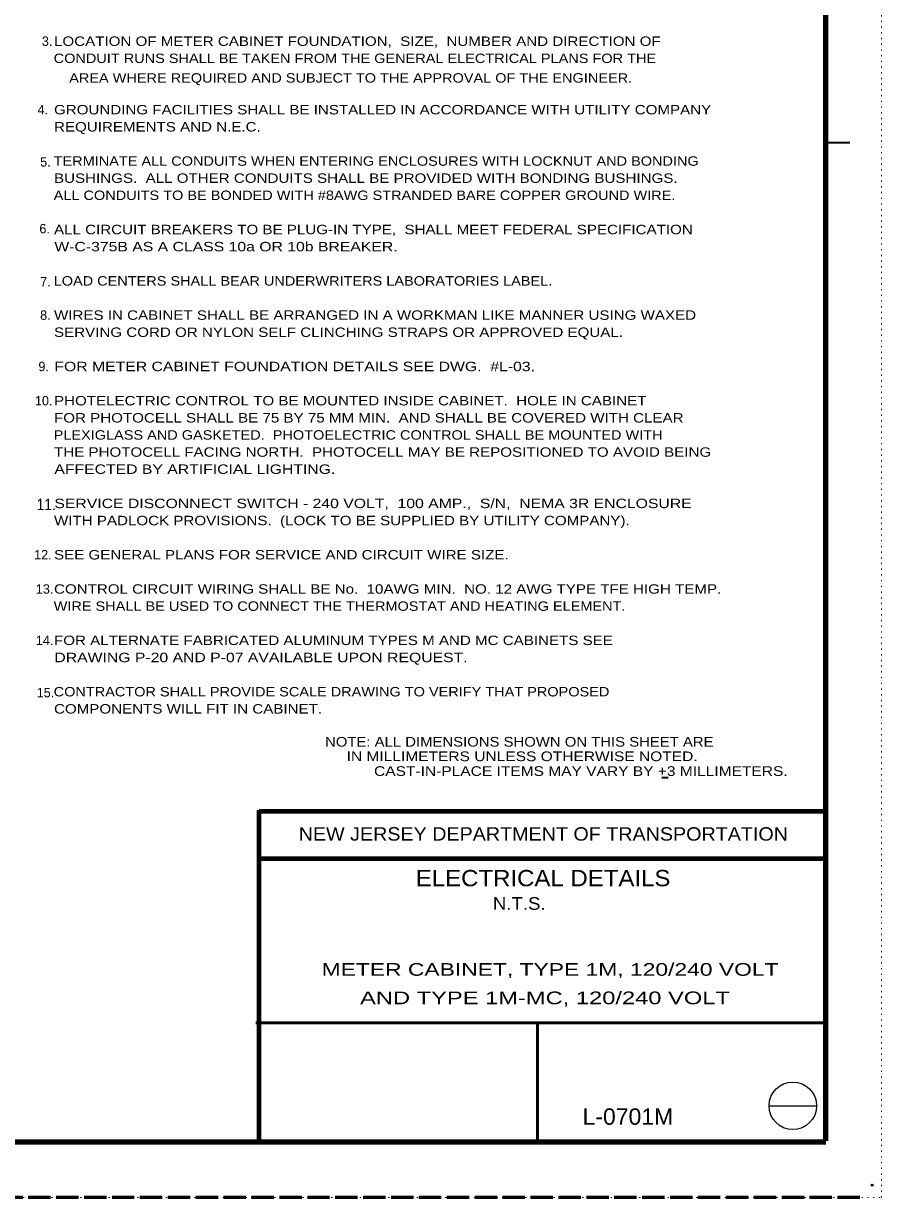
# Model space of a CAD drawing. Extents: x 312583 to 312854, y 144419 to 144597.
# Drawn here: x 312784.3 to 312853.5, y 144418.6 to 144513.2 of the extents above; entities that cross this region are included whole.
import ezdxf
from ezdxf.enums import TextEntityAlignment as Align

# ---------------------------------------------------------------- set-up
doc = ezdxf.new("R2010")
doc.units = 0
doc.header["$LTSCALE"] = 0.3
doc.header["$PDMODE"] = 32
doc.header["$PDSIZE"] = 0.15
doc.linetypes.add('DOTTED', pattern=[1.5, 0.3, -1.2])
doc.linetypes.add('LONG_DASHED', pattern=[7.5, 6, -1.5])
for name, color, linetype, lineweight in [('1', 7, 'Continuous', 25), ('2', 7, 'Continuous', 13), ('63', 7, 'DOTTED', 13)]:
    doc.layers.add(name, color=color, linetype=linetype, lineweight=lineweight)

msp = doc.modelspace()

# ---------------------------------------------------------------- linework, layer by layer
at = {"layer": '1', "lineweight": 158}
for p, q in [((312849, 144423.1446), (312849, 144585.0846)), ((312616.5, 144423.0846), (312849, 144423.0846))]:
    msp.add_line(p, q, dxfattribs=at)
at = {"layer": '1', "lineweight": 35}
for p, q in [((312849, 144503.6216), (312850.932, 144503.6216)), ((312835.7873, 144452.4577), (312836.2972, 144452.4577))]:
    msp.add_line(p, q, dxfattribs=at)
at = {"layer": '1', "lineweight": 80}
for p, q in [((312803.31, 144423.1446), (312803.31, 144449.8146)), ((312803.31, 144449.7246), (312849, 144449.7246)), ((312803.31, 144445.9146), (312849, 144445.9146))]:
    msp.add_line(p, q, dxfattribs=at)
at = {"layer": '1', "lineweight": 53}
for p, q in [((312849, 144432.6666), (312803.0384, 144432.6666)), ((312825.7547, 144432.6666), (312825.7547, 144423.1446))]:
    msp.add_line(p, q, dxfattribs=at)
at = {"layer": '1'}
msp.add_line((312844.4384, 144425.966), (312848.2794, 144425.966), dxfattribs=at)
at = {"layer": '1', "linetype": 'LONG_DASHED', "lineweight": 60}
msp.add_line((312851.75, 144418.5846), (312583.526, 144418.5846), dxfattribs=at)
at = {"layer": '1'}
msp.add_circle((312846.3494, 144425.9805), 1.9159, dxfattribs=at)
msp.add_point((312852.75, 144419.5846), dxfattribs=at)
at = {"layer": '63'}
msp.add_lwpolyline([(312601.2, 144418.5846), (312853.5, 144418.5846), (312853.5, 144596.7846)], dxfattribs=at)

# ---------------------------------------------------------------- texts
at = {"layer": '1'}
for s, width, p in [('NOTE: ALL DIMENSIONS SHOWN ON THIS SHEET ARE', 1.15, (312808.6294, 144454.9329)), ('     IN MILLIMETERS UNLESS OTHERWISE NOTED.', 1.2, (312808.6293, 144453.7629)), ('CAST-IN-PLACE ITEMS MAY VARY BY +3 MILLIMETERS.', 1.2, (312812.5802, 144452.572))]:
    msp.add_text(s, height=0.78, dxfattribs=dict(at, width=width)).set_placement(p)
for s, height, width, p in [('NEW JERSEY DEPARTMENT OF TRANSPORTATION', 1.08, 1.1, (312826.2285, 144447.3546)), ('ELECTRICAL DETAILS', 1.315, 1.1, (312826.2107, 144443.6759)), ('L-0701M', 1.319, 1.05, (312833.0487, 144424.4513))]:
    msp.add_text(s, height=height, dxfattribs=dict(at, width=width)).set_placement(p, align=Align.CENTER)
at = {"layer": '2'}
for s, p in [('3.', (312785.7968, 144511.4205)), ('4.', (312785.4465, 144505.9005)), ('5.', (312785.6567, 144501.6903)), ('6.', (312785.5919, 144496.3106)), ('7.', (312785.6567, 144492.0303)), ('8.', (312785.6568, 144489.3405)), ('9.', (312785.5166, 144485.2005)), ('10.', (312785.2349, 144482.4405)), ('12.', (312785.1691, 144470.0205)), ('13.', (312785.3091, 144467.2605)), ('14.', (312785.3091, 144463.1205)), ('15.', (312785.3792, 144458.9103))]:
    msp.add_text(s, height=0.76, dxfattribs=at).set_placement(p)
for s, width, p in [('  LOCATION OF METER CABINET FOUNDATION,  SIZE,  NUMBER AND DIRECTION OF  ', 1.2, (312786.097, 144511.4205)), ('  CONDUIT RUNS SHALL BE TAKEN FROM THE GENERAL ELECTRICAL PLANS FOR THE', 1.15, (312786.097, 144510.0405)), ('AREA WHERE REQUIRED AND SUBJECT TO THE APPROVAL OF THE ENGINEER.', 1.15, (312787.9983, 144508.4612)), ('  GROUNDING FACILITIES SHALL BE INSTALLED IN ACCORDANCE WITH UTILITY COMPANY  ', 1.2, (312786.097, 144505.9005)), ('  REQUIREMENTS AND N.E.C.                                                            ', 1.2, (312786.097, 144504.5205)), ('  TERMINATE ALL CONDUITS WHEN ENTERING ENCLOSURES WITH LOCKNUT AND BONDING   ', 1.15, (312786.097, 144501.7605)), ('  BUSHINGS.  ALL OTHER CONDUITS SHALL BE PROVIDED WITH BONDING BUSHINGS. ', 1.2, (312786.097, 144500.3805)), ('  ALL CONDUITS TO BE BONDED WITH #8AWG STRANDED BARE COPPER GROUND WIRE.  ', 1.15, (312786.097, 144499.0005)), ('  ALL CIRCUIT BREAKERS TO BE PLUG-IN TYPE,  SHALL MEET FEDERAL SPECIFICATION  ', 1.2, (312786.097, 144496.2405)), ('  W-C-375B AS A CLASS 10a OR 10b BREAKER.', 1.25, (312786.097, 144494.8605)), ('  LOAD CENTERS SHALL BEAR UNDERWRITERS LABORATORIES LABEL.  ', 1.15, (312786.097, 144492.1005)), ('  WIRES IN CABINET SHALL BE ARRANGED IN A WORKMAN LIKE MANNER USING WAXED    ', 1.2, (312786.097, 144489.3405)), ('  SERVING CORD OR NYLON SELF CLINCHING STRAPS OR APPROVED EQUAL.  ', 1.2, (312786.097, 144487.9605)), ('  FOR METER CABINET FOUNDATION DETAILS SEE DWG.  #L-03.   ', 1.25, (312786.097, 144485.2005)), ('  PHOTELECTRIC CONTROL TO BE MOUNTED INSIDE CABINET.  HOLE IN CABINET  ', 1.2, (312786.097, 144482.4405)), ('  FOR PHOTOCELL SHALL BE 75 BY 75 MM MIN.  AND SHALL BE COVERED WITH CLEAR ', 1.2, (312786.097, 144481.0605)), ('  PLEXIGLASS AND GASKETED.  PHOTOELECTRIC CONTROL SHALL BE MOUNTED WITH  ', 1.15, (312786.097, 144479.6805)), ('  THE PHOTOCELL FACING NORTH.  PHOTOCELL MAY BE REPOSITIONED TO AVOID BEING    ', 1.2, (312786.097, 144478.3005)), ('  AFFECTED BY ARTIFICIAL LIGHTING. ', 1.25, (312786.097, 144476.9205)), ('  SERVICE DISCONNECT SWITCH - 240 VOLT,  100 AMP.,  S/N,  NEMA 3R ENCLOSURE   ', 1.25, (312786.097, 144474.1605)), ('  WITH PADLOCK PROVISIONS.  (LOCK TO BE SUPPLIED BY UTILITY COMPANY).   ', 1.2, (312786.097, 144472.7805)), ('  SEE GENERAL PLANS FOR SERVICE AND CIRCUIT WIRE SIZE.  ', 1.2, (312786.097, 144470.0205)), ('  CONTROL CIRCUIT WIRING SHALL BE No.  10AWG MIN.  NO. 12 AWG TYPE TFE HIGH TEMP.', 1.2, (312786.097, 144467.2605)), ('  WIRE SHALL BE USED TO CONNECT THE THERMOSTAT AND HEATING ELEMENT.', 1.15, (312786.097, 144465.8805)), ('  FOR ALTERNATE FABRICATED ALUMINUM TYPES M AND MC CABINETS SEE ', 1.2, (312786.097, 144463.1205)), ('  DRAWING P-20 AND P-07 AVAILABLE UPON REQUEST.  ', 1.25, (312786.097, 144461.7405)), ('  CONTRACTOR SHALL PROVIDE SCALE DRAWING TO VERIFY THAT PROPOSED  ', 1.15, (312786.097, 144458.9805)), ('  COMPONENTS WILL FIT IN CABINET.', 1.2, (312786.097, 144457.6005))]:
    msp.add_text(s, height=0.76, dxfattribs=dict(at, width=width)).set_placement(p)
at = {"layer": '2', "width": 0.9}
msp.add_text('11.', height=0.92, dxfattribs=at).set_placement((312786.9173, 144474.0005), align=Align.RIGHT)
at = {"layer": '2'}
for s, width, p in [('    N.T.S.  ', 1.1, (312823.87, 144441.778)), ('    METER CABINET, TYPE 1M, 120/240 VOLT    ', 1.35, (312826.7743, 144436.4609)), ('        AND TYPE 1M-MC, 120/240 VOLT        ', 1.4, (312826.3641, 144434.1686))]:
    msp.add_text(s, height=1.02, dxfattribs=dict(at, width=width)).set_placement(p, align=Align.CENTER)

doc.saveas('drawing.dxf')
